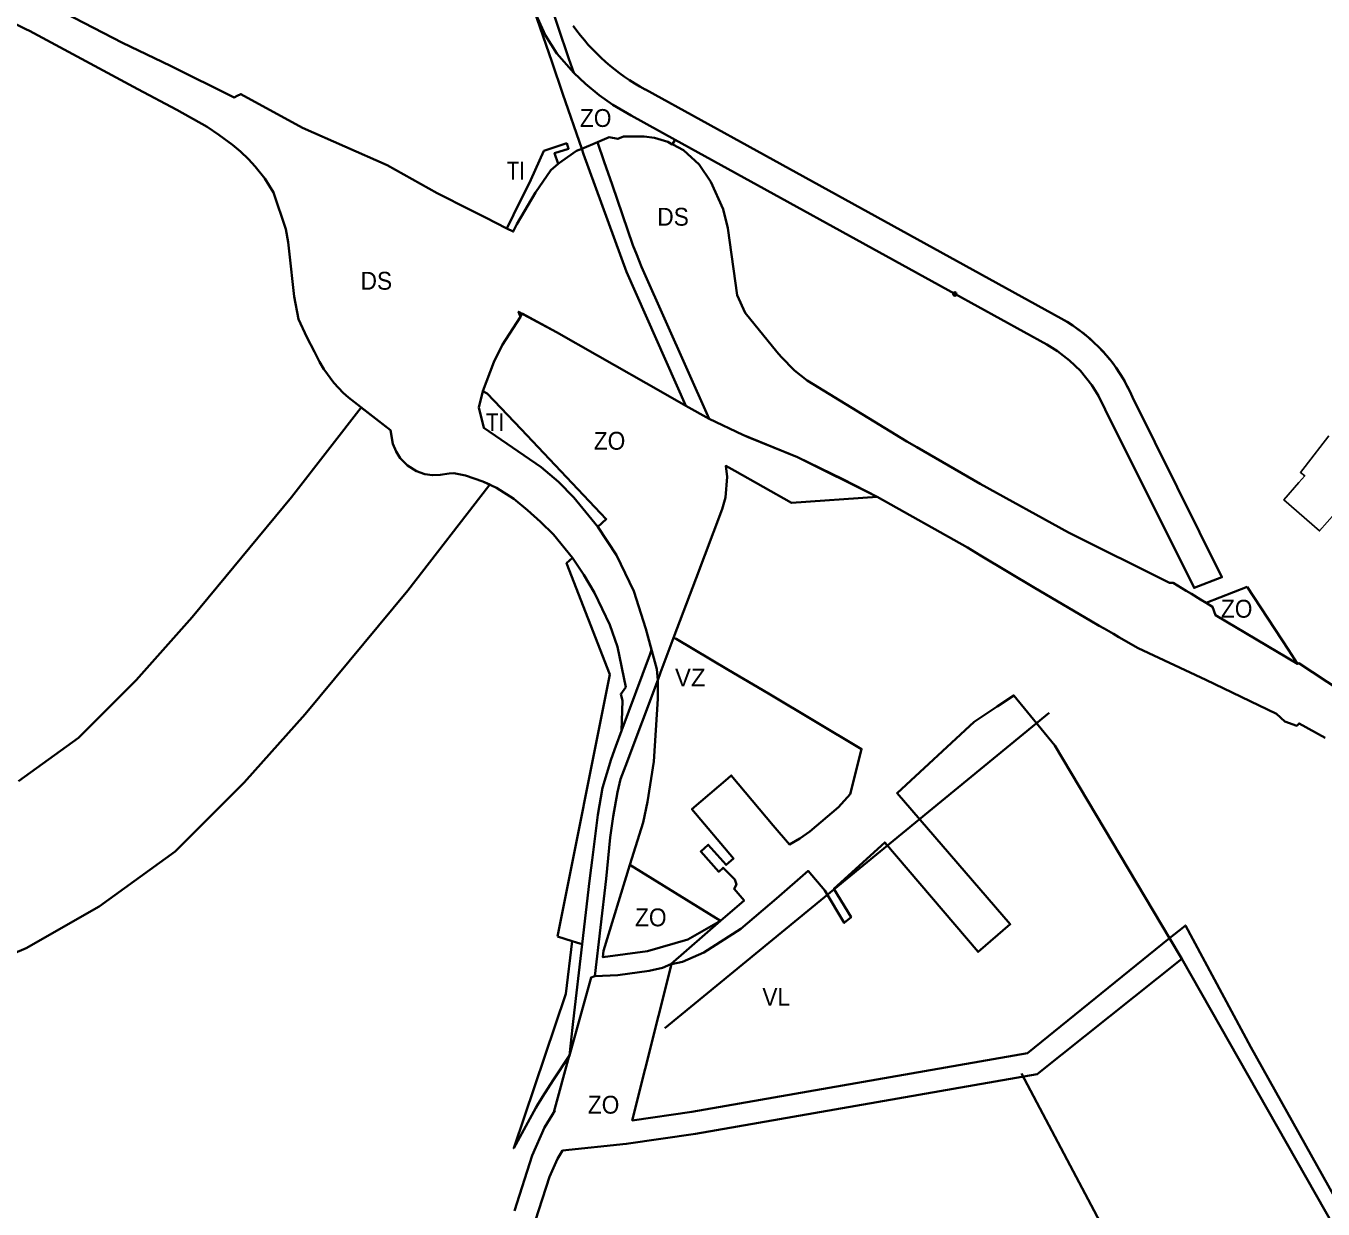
# Model space of a CAD drawing. Extents: x -650276 to -642489, y -1074311 to -1066658.
# Drawn here: x -646929 to -646058, y -1069228 to -1068433 of the extents above; entities that cross this region are included whole.
import ezdxf

# ---------------------------------------------------------------- set-up
doc = ezdxf.new("R2010")
doc.units = 0
doc.header["$LTSCALE"] = 4.8
doc.header["$PDMODE"] = 32
doc.header["$PDSIZE"] = 2.4
for name, color, linetype, lineweight in [('15', 7, 'Continuous', 35), ('24', 7, 'Continuous', 35), ('30', 7, 'Continuous', 35), ('34', 7, 'Continuous', 35), ('36', 7, 'Continuous', 35), ('42', 7, 'Continuous', 35), ('54', 7, 'Continuous', 35), ('61', 7, 'Continuous', 25)]:
    doc.layers.add(name, color=color, linetype=linetype, lineweight=lineweight)
doc.layers.add('62', color=7, linetype='Continuous')

msp = doc.modelspace()

# ---------------------------------------------------------------- linework, layer by layer
at = {"layer": '15'}
msp.add_lwpolyline([(-646037.99, -1069242.88), (-646107, -1069119.41), (-646150.87, -1069037.64), (-646152.26, -1069038.76), (-646161.484, -1069046.228), (-646153.307, -1069059.947), (-646025.14, -1069285.394)], dxfattribs=at)
at = {"layer": '24'}
for points in [[(-647419.713, -1068138.871), (-647405.71, -1068151.74), (-647372.38, -1068179.01), (-647337.74, -1068205.67), (-647334.62, -1068208.02), (-647307.39, -1068227.44), (-647281.64, -1068244.34), (-647234.11, -1068273.04), (-647230.83, -1068274.93), (-647174.56, -1068306.35), (-647142.788, -1068322.462), (-647130.29, -1068328.8), (-647079.16, -1068357.01), (-647032.91, -1068382.51), (-647029.23, -1068384.46), (-646997.06, -1068401.37), (-646929.56, -1068435.42), (-646927.06, -1068436.66)], [(-646598.635, -1068354.436), (-646579.62, -1068411.29), (-646564.78, -1068455.41), (-646561.544, -1068464.842)], [(-646598.635, -1068354.436), (-646579.62, -1068411.29), (-646564.78, -1068455.41), (-646561.544, -1068464.842)], [(-646634.37, -1068735.27), (-646622.62, -1068739.32), (-646613.44, -1068743.65), (-646601.86, -1068751.01), (-646592.53, -1068758.66), (-646583.98, -1068766.42), (-646575.28, -1068775.04), (-646562.49, -1068790.69), (-646554.8, -1068801.98), (-646547.68, -1068814.22), (-646537.35, -1068835.56), (-646532.16, -1068850.47), (-646526.64, -1068877.47), (-646530.06, -1068882.16), (-646528.92, -1068886.55), (-646529.44, -1068906.81), (-646510.56, -1068855.86), (-646509.323, -1068852.529), (-646513.27, -1068838.37), (-646521.18, -1068812.95), (-646532.92, -1068788.95), (-646545.32, -1068769.89), (-646561.5, -1068750.22), (-646571.91, -1068739.54), (-646583.49, -1068729.76), (-646622.01, -1068703.3), (-646625.35, -1068689.7), (-646622.68, -1068678.75), (-646615.19, -1068659.11), (-646609.7, -1068647.84), (-646597.4, -1068628.74), (-646596.28, -1068626.52), (-646596.28, -1068626.52), (-646573.14, -1068638.98), (-646545.73, -1068654.81), (-646545.73, -1068654.81), (-646501.64, -1068679.81), (-646486.23, -1068688.54), (-646526.1, -1068598.55), (-646555, -1068519.38), (-646555, -1068519.38), (-646556.22, -1068515.84), (-646559.72, -1068517.29), (-646569.61, -1068524.1), (-646572.02, -1068526.07), (-646577.07, -1068530.2), (-646587.28, -1068545.28), (-646599.75, -1068566.49), (-646602.21, -1068571.5), (-646606.59, -1068569.33), (-646620.94, -1068561.96), (-646625.86, -1068559.47), (-646631.18, -1068556.77), (-646653.21, -1068545.58), (-646686.84, -1068526.89), (-646686.84, -1068526.89), (-646743.69, -1068501.76), (-646785.05, -1068479.12), (-646787.55, -1068480.36), (-646789.49, -1068481.31), (-646832.29, -1068460.04), (-646864.48, -1068444.64), (-646936.47, -1068407.23)], [(-646927.06, -1068436.66), (-646854.18, -1068475.8), (-646828.2, -1068489.61), (-646807.82, -1068501.17), (-646799.79, -1068506.39), (-646790.66, -1068513.24), (-646785.34, -1068517.77), (-646779.93, -1068522.9), (-646775.44, -1068527.74), (-646768.95, -1068535.8), (-646763.1, -1068545.18), (-646754.92, -1068569.81), (-646753.35, -1068578.6), (-646752.59, -1068584.55), (-646749.35, -1068615.18), (-646746.32, -1068630.23), (-646740.91, -1068642.34), (-646735.62, -1068652.21), (-646732.25, -1068659.06), (-646729.34, -1068663.94), (-646722.6, -1068673.11), (-646716.39, -1068679.8), (-646716.39, -1068679.8), (-646712.93, -1068683), (-646684.7, -1068704.95), (-646682.98, -1068714.07), (-646680.88, -1068719.28), (-646678.08, -1068723.7), (-646673.16, -1068728.69), (-646667.17, -1068732.38), (-646667.17, -1068732.38), (-646661.5, -1068734.35), (-646656.47, -1068735.13), (-646651.21, -1068734.99), (-646645.18, -1068733.91), (-646642.04, -1068733.74), (-646634.37, -1068735.27)], [(-646561.544, -1068464.842), (-646553.677, -1068472.283), (-646544.525, -1068479.79), (-646535.245, -1068486.342), (-646523.105, -1068493.54), (-646493.511, -1068509.855), (-646305.678, -1068613.404)], [(-646561.544, -1068464.842), (-646553.677, -1068472.283), (-646544.525, -1068479.79), (-646535.245, -1068486.342), (-646523.105, -1068493.54), (-646493.511, -1068509.855), (-646305.678, -1068613.404)], [(-646234.342, -1068629.893), (-646234.342, -1068629.892), (-646438.626, -1068517.274), (-646513.45, -1068476.025), (-646513.567, -1068475.963)], [(-646234.342, -1068629.893), (-646234.342, -1068629.892), (-646438.626, -1068517.274), (-646513.45, -1068476.025), (-646513.567, -1068475.963)], [(-646337.93, -1068712.4), (-646404.83, -1068671.52), (-646413.45, -1068664.71), (-646422.32, -1068655.58), (-646425.11, -1068652.37), (-646446.54, -1068626.14), (-646451.82, -1068614.31), (-646458.03, -1068569.26), (-646461.14, -1068556.34), (-646469.51, -1068538.15), (-646477.41, -1068526.45), (-646487.92, -1068516.87), (-646498.48, -1068511.26), (-646507.4, -1068508.45), (-646514.39, -1068507.56), (-646528.18, -1068507.58), (-646531.9, -1068509.25), (-646537.71, -1068508.16), (-646545.57, -1068511.42), (-646541.06, -1068524.58), (-646535.84, -1068539.8), (-646521.81, -1068580.69), (-646519.14, -1068587.06), (-646516.07, -1068595.08), (-646515.09, -1068597.29), (-646470.65, -1068697.38), (-646448.02, -1068707.99), (-646444.51, -1068709.64), (-646411.3, -1068723.11), (-646380.94, -1068737.81), (-646357.87, -1068749.64), (-646297.08, -1068783.8), (-646288.37, -1068789.04), (-646251.73, -1068811.04), (-646214.92, -1068832.85), (-646208.7, -1068836.39), (-646205.48, -1068838.23), (-646199.24, -1068841.79), (-646195.52, -1068843.92), (-646182.57, -1068851.3)], [(-646305.678, -1068613.404), (-646243.997, -1068647.407), (-646236.707, -1068651.891), (-646228.691, -1068658.051), (-646221.348, -1068665.144), (-646213.659, -1068674.696), (-646209.179, -1068681.795), (-646204.654, -1068690.937), (-646145.083, -1068810.83), (-646126.317, -1068803.654), (-646186.371, -1068682.825)], [(-646305.678, -1068613.404), (-646243.997, -1068647.407), (-646236.707, -1068651.891), (-646228.691, -1068658.051)], [(-646228.691, -1068658.051), (-646221.348, -1068665.144), (-646213.659, -1068674.696), (-646209.179, -1068681.795), (-646204.654, -1068690.937), (-646145.083, -1068810.83), (-646126.317, -1068803.654), (-646186.371, -1068682.825)], [(-646978.92, -1069073.93), (-646929.186, -1069052.925), (-646880.163, -1069024.903), (-646829.104, -1068987.917), (-646782.784, -1068941.581), (-646741.85, -1068895.719), (-646673.05, -1068812.491), (-646618.655, -1068742.359), (-646617.991, -1068741.503), (-646622.62, -1068739.32), (-646634.37, -1068735.27), (-646642.04, -1068733.74), (-646645.18, -1068733.91), (-646651.21, -1068734.99), (-646656.47, -1068735.13), (-646661.5, -1068734.35), (-646667.17, -1068732.38), (-646673.16, -1068728.69), (-646678.08, -1068723.7), (-646680.88, -1068719.28), (-646682.98, -1068714.07), (-646684.7, -1068704.95), (-646704.316, -1068689.698), (-646725.374, -1068716.786), (-646751.116, -1068749.975), (-646817.718, -1068830.545), (-646855.506, -1068872.883), (-646894.206, -1068911.595), (-646934.465, -1068940.759)], [(-646046.48, -1068879.92), (-646074.78, -1068861.51), (-646075.56, -1068861.95), (-646130.68, -1068829.21), (-646132.62, -1068823.54), (-646136.99, -1068820.88), (-646140.73, -1068818.61), (-646146.85, -1068814.88), (-646150.26, -1068812.81), (-646159.1, -1068807.43), (-646161.45, -1068807.54), (-646229.44, -1068773.53), (-646288.59, -1068740.88), (-646331.26, -1068716.25), (-646337.93, -1068712.4)], [(-646182.57, -1068851.3), (-646137.23, -1068872.6), (-646089.63, -1068895.5), (-646084.1, -1068900.51), (-646076.09, -1068903.48), (-646074.51, -1068901.9), (-646057.13, -1068911.62)], [(-646505.17, -1068872.78), (-646526.81, -1068930.69), (-646530.08, -1068939.43), (-646532.13, -1068948), (-646535.13, -1068964.38), (-646537.02, -1068978.44), (-646539.77, -1069006.25), (-646547.412, -1069071.71), (-646532, -1069071)], [(-646505.17, -1068872.78), (-646526.81, -1068930.69), (-646530.08, -1068939.43), (-646532.13, -1068948), (-646535.13, -1068964.38), (-646537.02, -1068978.44), (-646539.77, -1069006.25)], [(-646524, -1068997), (-646514.91, -1068968.48), (-646514.91, -1068968.48), (-646512.07, -1068954.68), (-646507.91, -1068927.47), (-646505.12, -1068885.31), (-646505.17, -1068872.78)], [(-646524, -1068997), (-646514.91, -1068968.48), (-646514.91, -1068968.48), (-646512.07, -1068954.68), (-646507.91, -1068927.47), (-646505.12, -1068885.31), (-646505.17, -1068872.78)], [(-646462.98, -1069034.61), (-646485, -1069047), (-646512, -1069055), (-646542, -1069059), (-646541.71, -1069054.76), (-646524, -1068997)], [(-646512, -1069055), (-646542, -1069059), (-646541.71, -1069054.76), (-646524, -1068997)], [(-646539.77, -1069006.25), (-646539.77, -1069006.25), (-646547.412, -1069071.71)], [(-646547.412, -1069071.71), (-646532, -1069071), (-646511, -1069068), (-646502, -1069066), (-646496.317, -1069063.61), (-646462.98, -1069034.61)], [(-646532, -1069071), (-646511, -1069068), (-646502, -1069066), (-646496.317, -1069063.61), (-646462.98, -1069034.61), (-646485, -1069047), (-646512, -1069055)]]:
    msp.add_lwpolyline(points, dxfattribs=at)
msp.add_lwpolyline([(-646582.46, -1069152.81), (-646575.4, -1069141.46), (-646564.54, -1069125.08), (-646562.35, -1069106.21), (-646561.88, -1069102.18), (-646555.84, -1069050.22), (-646555.84, -1069050.22), (-646559.8, -1069048.98), (-646562.61, -1069048.08), (-646566.82, -1069083.62), (-646601.82, -1069187.25), (-646586.97, -1069160.06), (-646585.42, -1069157.56), (-646583.89, -1069155.1), (-646582.46, -1069152.81)], close=True, dxfattribs=at)
for centre, radius, start, end in [((-646447.332, -1068351.964), 140.58, 215.36631, 241.891), ((-646447.332, -1068351.964), 140.58, 215.36642, 241.891), ((-646287.447, -1068726.224), 110, 23.23727, 61.13296), ((-646287.447, -1068726.224), 110, 57.43148, 61.13296), ((-646287.447, -1068726.224), 110, 23.23727, 57.43149)]:
    msp.add_arc(centre, radius, start, end, dxfattribs=at)
msp.add_point((-646305.678, -1068613.404), dxfattribs=at)
at = {"layer": '30'}
msp.add_line((-646583.49, -1068729.76), (-646571.91, -1068739.54), dxfattribs=at)
for points in [[(-646566.33, -1068512.04), (-646581.64, -1068517.24), (-646590.31, -1068536.69), (-646602.01, -1068560.15), (-646606.59, -1068569.33)], [(-646587.28, -1068545.28), (-646577.07, -1068530.2), (-646572.02, -1068526.07), (-646574.48, -1068518.75), (-646565.04, -1068515.86), (-646566.33, -1068512.04)], [(-646599.75, -1068566.49), (-646587.28, -1068545.28), (-646587.28, -1068545.28)], [(-646606.59, -1068569.33), (-646602.21, -1068571.5), (-646599.75, -1068566.49)], [(-646571.91, -1068739.54), (-646561.5, -1068750.22), (-646545.32, -1068769.89), (-646539.78, -1068764.65), (-646596.93, -1068704.15), (-646619.74, -1068680.15), (-646622.68, -1068678.75), (-646625.35, -1068689.7)], [(-646625.35, -1068689.7), (-646622.01, -1068703.3), (-646583.49, -1068729.76)], [(-646562.49, -1068790.69), (-646566.34, -1068794.32), (-646537.3, -1068868.95), (-646572.42, -1069044.94)], [(-646526.64, -1068877.47), (-646532.16, -1068850.47), (-646537.35, -1068835.56), (-646547.68, -1068814.22), (-646554.8, -1068801.98), (-646562.49, -1068790.69)], [(-646529.44, -1068906.81), (-646528.92, -1068886.55), (-646530.06, -1068882.16), (-646526.64, -1068877.47)], [(-646555.84, -1069050.22), (-646550.89, -1069007.7), (-646549.81, -1068998.88), (-646549.17, -1068993.71), (-646545.42, -1068963.3), (-646542.16, -1068945.12), (-646536.54, -1068925.95), (-646533.28, -1068917.17), (-646529.44, -1068906.81)], [(-646572.42, -1069044.94), (-646562.61, -1069048.08), (-646559.8, -1069048.98), (-646555.84, -1069050.22)]]:
    msp.add_lwpolyline(points, dxfattribs=at)
at = {"layer": '34'}
msp.add_lwpolyline([(-646161.484, -1069046.228), (-646238.632, -1068916.799), (-646266.118, -1068883.048), (-646277.268, -1068890.446), (-646292.75, -1068900.72), (-646344.49, -1068948.736), (-646268.528, -1069036.82), (-646290.099, -1069055.423), (-646352.71, -1068981.82), (-646386.936, -1069012.936), (-646375.346, -1069032.07), (-646379.973, -1069035.889), (-646393.09, -1069014.234), (-646404.269, -1069001.033), (-646425.52, -1069019.41), (-646449.418, -1069039.804), (-646474.13, -1069055.83), (-646488.537, -1069062.169), (-646495.89, -1069063.531), (-646522.35, -1069168.648), (-646482.211, -1069162.813), (-646256.824, -1069123.414)], close=True, dxfattribs=at)
at = {"layer": '36'}
msp.add_lwpolyline([(-646512.07, -1068954.68), (-646507.91, -1068927.47), (-646505.12, -1068885.31), (-646505.17, -1068872.78), (-646503.24, -1068867.61), (-646494.52, -1068844.29), (-646492.73, -1068845.01), (-646457.86, -1068865.8), (-646430.86, -1068881.89), (-646368.3, -1068919.19), (-646376.02, -1068949.34), (-646383.86, -1068958.24), (-646403.13, -1068974.41), (-646409.67, -1068979.3), (-646416.71, -1068983.21), (-646427.77, -1068970.39), (-646455.78, -1068936.87), (-646458.21, -1068938.99), (-646482.2, -1068959.52), (-646454.21, -1068992.73), (-646459.25, -1068996.98), (-646471.24, -1068983.41), (-646476.35, -1068987.98), (-646464.24, -1069001.49), (-646461.29, -1068998.81), (-646453.48, -1069006.75), (-646452.37, -1069010.01), (-646453.88, -1069013.1), (-646447.2, -1069020.9), (-646462.98, -1069034.61), (-646524, -1068997), (-646514.91, -1068968.48), (-646514.91, -1068968.48)], close=True, dxfattribs=at)
at = {"layer": '42'}
for points in [[(-646561.544, -1068464.842), (-646572.984, -1068451.81), (-646580.625, -1068439.803), (-646588.07, -1068422.96), (-646576.4, -1068457.27), (-646568.87, -1068479.14), (-646556.22, -1068515.84), (-646545.57, -1068511.42), (-646537.71, -1068508.16)], [(-646523.105, -1068493.54), (-646535.245, -1068486.342), (-646544.525, -1068479.79), (-646553.677, -1068472.283), (-646561.544, -1068464.842)], [(-646537.71, -1068508.16), (-646531.9, -1068509.25), (-646528.18, -1068507.58), (-646514.39, -1068507.56), (-646507.4, -1068508.45), (-646498.48, -1068511.26), (-646495.416, -1068512.888), (-646493.511, -1068509.855), (-646523.105, -1068493.54)], [(-646075.56, -1068861.95), (-646130.68, -1068829.21), (-646132.62, -1068823.54), (-646136.99, -1068820.88), (-646109.35, -1068810.23)], [(-646109.35, -1068810.23), (-646081.72, -1068852.51), (-646075.56, -1068861.95)], [(-646611.107, -1069309.68), (-646577.878, -1069206.485), (-646572.586, -1069194.485), (-646569.114, -1069188.86), (-646526.31, -1069184.381), (-646479.84, -1069177.626), (-646250.409, -1069137.52), (-646153.307, -1069059.947), (-646161.484, -1069046.228), (-646256.824, -1069123.414), (-646482.211, -1069162.813), (-646522.35, -1069168.648), (-646495.89, -1069063.531), (-646496.317, -1069063.61), (-646496.317, -1069063.61), (-646502, -1069066), (-646511, -1069068), (-646532, -1069071), (-646547.412, -1069071.71), (-646549.91, -1069072.542), (-646564.54, -1069125.08), (-646564.605, -1069125.271), (-646574.978, -1069163.017), (-646574.978, -1069163.017), (-646574.33, -1069162.04), (-646575.87, -1069164.54), (-646581.29, -1069173.32), (-646589.56, -1069192.07), (-646601.41, -1069229.34)]]:
    msp.add_lwpolyline(points, dxfattribs=at)
for points in [[(-646609.7, -1068647.84), (-646615.19, -1068659.11), (-646622.68, -1068678.75), (-646619.74, -1068680.15), (-646596.93, -1068704.15), (-646539.78, -1068764.65), (-646545.32, -1068769.89), (-646532.92, -1068788.95), (-646521.18, -1068812.95), (-646513.27, -1068838.37), (-646505.69, -1068865.56), (-646505.17, -1068872.78), (-646503.24, -1068867.61), (-646494.52, -1068844.29), (-646479.45, -1068804.37), (-646461.92, -1068757.93), (-646459.59, -1068750.19), (-646458.57, -1068736.31), (-646459.54, -1068728.94), (-646453.51, -1068732.3), (-646415.3, -1068753.62), (-646357.87, -1068749.64), (-646411.3, -1068723.11), (-646448.02, -1068707.99), (-646470.65, -1068697.38), (-646486.23, -1068688.54), (-646501.64, -1068679.81), (-646545.73, -1068654.81), (-646573.14, -1068638.98), (-646598.59, -1068625.34), (-646597.4, -1068628.74)], [(-646541.71, -1069054.76), (-646542, -1069059), (-646512, -1069055), (-646485, -1069047), (-646462.98, -1069034.61), (-646524, -1068997)]]:
    msp.add_lwpolyline(points, close=True, dxfattribs=at)
at = {"layer": '54'}
for p, q in [((-646500.355, -1069106.714), (-646242.413, -1068894.833)), ((-646261, -1069137), (-646156.539, -1069334.511))]:
    msp.add_line(p, q, dxfattribs=at)
at = {"layer": '61'}
msp.add_lwpolyline([(-646050.57, -1068760.83), (-646060.78, -1068772.53), (-646084.74, -1068751.8), (-646074.61, -1068740.08), (-646070.697, -1068735.553), (-646073.6, -1068733.3), (-646070.57, -1068729.39), (-646054.6, -1068708.79)], dxfattribs=at)

# ---------------------------------------------------------------- texts
at = {"layer": '62'}
for s, width, p in [('ZO', 0.95, (-646557.423, -1068501.188)), ('TI', 0.85, (-646606.476, -1068536.535)), ('DS', 0.95, (-646505.476, -1068567.535)), ('DS', 0.95, (-646704.709, -1068610.535)), ('TI', 0.85, (-646620.476, -1068705.535)), ('ZO', 0.95, (-646548.118, -1068718.035)), ('ZO', 0.95, (-646127.027, -1068830.859)), ('ZO', 0.95, (-646520.423, -1069038.188)), ('VL', 0.95, (-646434.928, -1069091.6)), ('ZO', 0.95, (-646552.118, -1069164.035))]:
    msp.add_text(s, height=12, dxfattribs=dict(at, width=width)).set_placement(p)
msp.add_text('VZ', height=12, dxfattribs=at).set_placement((-646493.598, -1068877.069))

doc.saveas('drawing.dxf')
